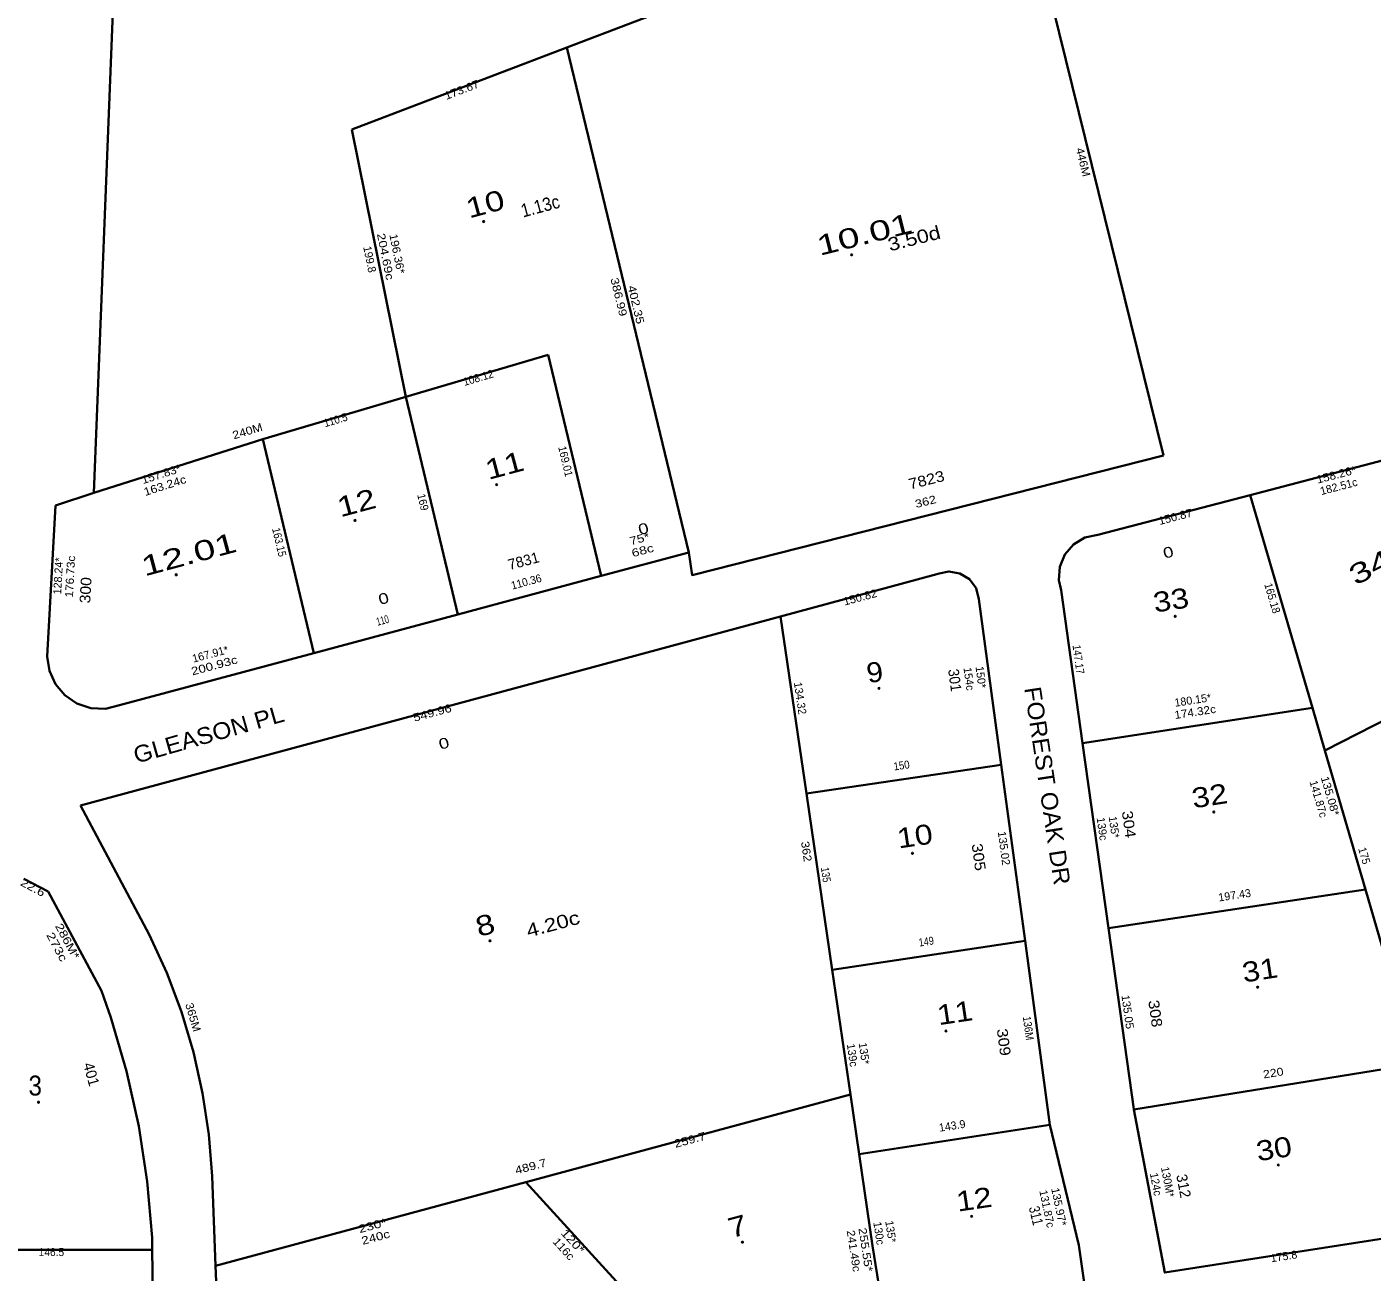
# Model space of a CAD drawing. Extents: x 2546959 to 2550387, y 581906 to 585027.
# Drawn here: x 2548228 to 2549237, y 583358 to 584292 of the extents above; entities that cross this region are included whole.
import ezdxf
from ezdxf.enums import TextEntityAlignment as Align

# ---------------------------------------------------------------- set-up
doc = ezdxf.new("R2010")
doc.units = 0
doc.header["$LTSCALE"] = 2.4
doc.header["$PDMODE"] = 32
doc.header["$PDSIZE"] = 1.2
for name, color, linetype in [('20', 7, 'Continuous'), ('38', 7, 'Continuous'), ('39', 7, 'Continuous'), ('41', 7, 'Continuous'), ('42', 7, 'Continuous')]:
    doc.layers.add(name, color=color, linetype=linetype)
doc.layers.add('40', color=7, linetype='Continuous', lineweight=35)

msp = doc.modelspace()

# ---------------------------------------------------------------- linework, layer by layer
at = {"layer": '40'}
for p, q in [((2548310.336, 584755.908), (2548278.336, 583942.322)), ((2548632.906, 584276.263), (2548972.05, 584405.537)), ((2548471.7, 584214.815), (2548632.906, 584276.263)), ((2548632.906, 584276.263), (2548724.329, 583897.607)), ((2548512.325, 584014.19), (2548471.7, 584214.815)), ((2548658.645, 583879.97), (2548619.071, 584045.736)), ((2548512.325, 584014.19), (2548405.115, 583982.508)), ((2548405.115, 583982.508), (2548278.336, 583942.322)), ((2548405.115, 583982.508), (2548443.168, 583822.113)), ((2549145.332, 583940.621), (2549272.401, 583973.833)), ((2548278.336, 583942.322), (2548249.659, 583932.695)), ((2549031.214, 583910.794), (2549145.332, 583940.621)), ((2549145.332, 583940.621), (2549192.015, 583780.951)), ((2548249.659, 583932.695), (2548243.372, 583819.636)), ((2548658.645, 583879.97), (2548724.329, 583897.607)), ((2548551.317, 583851.152), (2548658.645, 583879.97)), ((2548793.282, 583849.522), (2548910.499, 583881.177)), ((2549019.704, 583754.571), (2549003.678, 583869.22)), ((2548268.244, 583707.733), (2548793.282, 583849.522)), ((2548443.168, 583822.113), (2548551.317, 583851.152)), ((2548793.282, 583849.522), (2548812.656, 583716.826)), ((2548297.603, 583782.942), (2548443.168, 583822.113)), ((2549192.015, 583780.951), (2549019.704, 583754.571)), ((2549192.015, 583780.951), (2549201.357, 583749)), ((2549039.085, 583615.922), (2549019.704, 583754.571)), ((2548268.244, 583707.733), (2548319.879, 583611.016)), ((2548225.941, 583652.934), (2548244.139, 583643.253)), ((2549231.828, 583644.78), (2549039.085, 583615.922)), ((2548244.139, 583643.253), (2548284.022, 583568.754)), ((2549058.078, 583480.042), (2549039.085, 583615.922)), ((2548976.581, 583606.27), (2548995.202, 583468.491)), ((2549058.078, 583480.042), (2549058.121, 583479.818)), ((2548995.202, 583468.491), (2548852.159, 583446.26)), ((2548995.202, 583468.491), (2549016.87, 583378.193)), ((2548602.241, 583425.464), (2548369.6, 583362.624)), ((2548173.506, 583374.598), (2548322.179, 583374.593)), ((2548871.845, 583317.439), (2548862.168, 583377.706)), ((2549016.87, 583378.193), (2549022.401, 583339.578))]:
    msp.add_line(p, q, dxfattribs=at)
for points in [[(2548972.05, 584405.537), (2548972.954, 584405.881), (2549080.399, 583970.174)], [(2548619.071, 584045.736), (2548512.325, 584014.19), (2548551.317, 583851.152)], [(2548724.329, 583897.607), (2548726.889, 583880.611), (2549080.399, 583970.174)], [(2549003.678, 583869.22), (2549001.94, 583876.807), (2549002.568, 583886.777), (2549006.338, 583896.027), (2549012.857, 583903.596), (2549021.447, 583908.695), (2549031.214, 583910.794)], [(2548910.499, 583881.177), (2548912.166, 583881.737), (2548919.412, 583883.309), (2548927.705, 583881.91), (2548934.869, 583877.503), (2548939.857, 583870.73), (2548941.941, 583862.582)], [(2548941.941, 583862.582), (2548958.719, 583738.442), (2548976.581, 583606.27)], [(2549361.129, 583830.668), (2549201.357, 583749), (2549231.828, 583644.78), (2549250.655, 583580.386)], [(2548297.603, 583782.942), (2548286.951, 583780.42), (2548276.014, 583780.894), (2548265.62, 583784.329), (2548256.554, 583790.463), (2548249.501, 583798.834), (2548244.993, 583808.81), (2548243.372, 583819.636)], [(2548958.719, 583738.442), (2548812.656, 583716.826), (2548831.943, 583584.719)], [(2548319.879, 583611.016), (2548332.974, 583582.446), (2548344.033, 583553.027), (2548353, 583522.905), (2548359.831, 583492.227), (2548364.494, 583461.146), (2548366.966, 583429.815)], [(2548976.581, 583606.27), (2548831.943, 583584.719), (2548845.598, 583491.199)], [(2548284.022, 583568.754), (2548290.963, 583548.887), (2548302.841, 583508.518), (2548312.007, 583467.447), (2548318.419, 583425.856), (2548322.049, 583383.932)], [(2549270.052, 583514.047), (2549058.121, 583479.818), (2549081.302, 583357.597), (2549259.719, 583385.325)], [(2548845.598, 583491.199), (2548602.241, 583425.464), (2548680.492, 583339.561)], [(2548845.598, 583491.199), (2548852.159, 583446.26), (2548862.168, 583377.706)], [(2548366.966, 583429.815), (2548369.6, 583362.624), (2548371.931, 583303.172)], [(2548322.049, 583383.932), (2548322.179, 583374.593), (2548323.315, 583293.027)]]:
    msp.add_lwpolyline(points, dxfattribs=at)
at = {"layer": '41'}
for p in [(2548570.661, 584145.703), (2548846.468, 584120.717), (2548580.312, 583948.378), (2548474.143, 583921.567), (2548340.092, 583880.814), (2549089.131, 583849.719), (2548867.019, 583795.638), (2549118.102, 583702.931), (2548892.127, 583672.028), (2548575.376, 583606.359), (2549150.936, 583571.594), (2548917.235, 583538.76), (2548236.848, 583485.331), (2549166.387, 583438.327), (2548936.549, 583399.697), (2548764.653, 583380.383)]:
    msp.add_point(p, dxfattribs=at)

# ---------------------------------------------------------------- texts
at = {"layer": '20', "width": 1.1}
for s, rotation, p in [('FOREST OAK DR', 278.597, (2548987.115, 583721.671)), ('GLEASON PL', 15.913, (2548366.146, 583755.161))]:
    msp.add_text(s, height=12.5, rotation=rotation, dxfattribs=at).set_placement(p, align=Align.CENTER)
at = {"layer": '38'}
for s, rotation, width, p in [('10', 15.03, 1.3, (2548573.686, 584151.698)), ('10.01', 14.217, 1.45, (2548857.843, 584128.848)), ('11', 15.03, 1.3, (2548588.129, 583955.653)), ('12', 15.03, 1.3, (2548477.154, 583927.593)), ('12.01', 15.03, 1.45, (2548351.457, 583888.976)), ('34', 27.074, 1.45, (2549238.674, 583879.825)), ('33', 8.834, 1.2, (2549087.084, 583854.487)), ('9', 8.418, 1.1, (2548864.951, 583800.401)), ('32', 8.834, 1.2, (2549116.043, 583707.715)), ('10', 8.418, 1.2, (2548894.977, 583677.502)), ('8', 15.116, 1.25, (2548573.663, 583611.009)), ('31', 8.834, 1.2, (2549153.745, 583577.065)), ('11', 8.418, 1.2, (2548925.003, 583545.002)), ('30', 8.834, 1.2, (2549164.308, 583443.078)), ('12', 8.418, 1.2, (2548939.403, 583405.184)), ('7', 15.116, 1.25, (2548762.939, 583385.091))]:
    msp.add_text(s, height=15, rotation=rotation, dxfattribs=dict(at, width=width)).set_placement(p, align=Align.CENTER)
at = {"layer": '38', "width": 0.9}
msp.add_text('3', height=15, dxfattribs=at).set_placement((2548234.368, 583490.331), align=Align.CENTER)
at = {"layer": '39'}
for s, rotation, width, p in [('7823', 14.217, 1.15, (2548903.6, 583948.07)), ('0', 15.03, 1.3, (2548691.447, 583911.528)), ('0', 14.648, 1.3, (2549084.935, 583893.801)), ('300', 86.817, 1.1, (2548276.103, 583869.032)), ('0', 15.03, 1.3, (2548496.623, 583859.155)), ('301', 277.697, 0.95, (2548919.95, 583801.259)), ('0', 15.113, 1.3, (2548541.859, 583750.574)), ('304', 277.958, 1.15, (2549050.494, 583693.208)), ('305', 277.697, 1.15, (2548937.901, 583668.602)), ('308', 277.957, 1.15, (2549070.334, 583551.235)), ('309', 277.697, 1.15, (2548956.675, 583529.832)), ('311', 283.493, 0.8, (2548980.952, 583399.362))]:
    msp.add_text(s, height=8, rotation=rotation, dxfattribs=dict(at, width=width)).set_placement(p, align=Align.CENTER)
for s, rotation, p in [('7831', 15.03, (2548601.537, 583887.365)), ('401', 285.442, (2548272.632, 583505.239)), ('312', 280.74, (2549091.529, 583421.792))]:
    msp.add_text(s, height=8, rotation=rotation, dxfattribs=at).set_placement(p, align=Align.CENTER)
at = {"layer": '42'}
for s, rotation, width, p in [('173.67', 20.866, 1.1, (2548555.269, 584241.682)), ('446M', 283.853, 1.1, (2549017.197, 584189.551)), ('204.69c', 281.447, 1.25, (2548494.08, 584118.863)), ('196.36*', 281.447, 1.1, (2548502.858, 584120.94)), ('386.99', 283.574, 1.2, (2548669.084, 584088.459)), ('402.35', 283.362, 1.2, (2548681.983, 584082.721)), ('108.12', 16.463, 0.95, (2548567.419, 584025.694)), ('110.5', 16.463, 0.9, (2548460.435, 583994.015)), ('240M', 17.074, 1.15, (2548394.396, 583985.724)), ('169.01', 283.427, 0.95, (2548629.159, 583965.205)), ('157.83*', 17.767, 1.1, (2548329.732, 583953.429)), ('158.26*', 14.648, 1.1, (2549210.627, 583952.991)), ('163.24c', 17.767, 1.15, (2548332.506, 583944.896)), ('169', 283.45, 0.95, (2548522.22, 583934.6)), ('362', 14.217, 1.2, (2548902.686, 583932.802)), ('150.87', 14.648, 1.05, (2549089.988, 583921.418)), ('163.15', 283.347, 0.9, (2548414.452, 583904.578)), ('75*', 15.03, 1.25, (2548688.212, 583904.888)), ('68c', 15.03, 1.3, (2548690.559, 583896.142)), ('176.73c', 86.817, 1.1, (2548263.512, 583879.357)), ('110.36', 15.03, 0.95, (2548603.324, 583872.693)), ('150.82', 15.112, 1.05, (2548853.666, 583861.06)), ('165.18', 286.297, 0.95, (2549159.111, 583862.459)), ('110', 15.03, 0.7, (2548495.591, 583843.785)), ('147.17', 277.957, 0.9, (2549013.66, 583816.936)), ('200.93c', 15.061, 1.25, (2548369.446, 583809.956)), ('549.96', 15.113, 1.2, (2548532.915, 583774.438)), ('174.32c', 8.704, 1.1, (2549104.517, 583775.026)), ('150', 8.418, 0.9, (2548884.384, 583734.914)), ('135.08*', 286.298, 1.1, (2549202.469, 583714.152)), ('135.02', 277.697, 1.05, (2548957.815, 583675.363)), ('362', 278.307, 1.15, (2548809.668, 583672.898)), ('175', 286.298, 0.95, (2549228.068, 583669.351)), ('135', 278.307, 0.85, (2548824.28, 583655.458)), ('22.6', 331.989, 1.25, (2548231.249, 583643.699)), ('286M*', 298.162, 1.25, (2548255.922, 583604.693)), ('273c', 298.162, 1.35, (2548248.028, 583600.426)), ('149', 8.474, 0.85, (2548902.894, 583602.863)), ('135.05', 277.957, 1.05, (2549050.564, 583552.67)), ('365M', 286.367, 1.1, (2548349.895, 583548.215)), ('136M', 277.697, 0.9, (2548976.055, 583540.431)), ('220', 9.175, 1.15, (2549163.125, 583504.377)), ('259.7', 15.116, 1.2, (2548726.085, 583454.229)), ('489.7', 15.116, 1.2, (2548606.674, 583434.283)), ('135.97*', 281.914, 1.05, (2548999.074, 583406.34)), ('230*', 15.116, 1.3, (2548488.062, 583389.909)), ('240c', 15.116, 1.25, (2548490.408, 583381.163)), ('116c', 312.331, 1.1, (2548628.436, 583373.326)), ('120*', 312.331, 1.3, (2548635.304, 583379.02)), ('241.49c', 278.734, 1.1, (2548845.192, 583373.391)), ('255.55*', 278.734, 1.2, (2548854.103, 583374.297)), ('146.5', 359.998, 0.95, (2548246.497, 583369.967))]:
    msp.add_text(s, height=5.999, rotation=rotation, dxfattribs=dict(at, width=width)).set_placement(p, align=Align.CENTER)
for s, rotation, width, p in [('1.13c', 15.03, 0.9, (2548600.11, 584148.681)), ('3.50d', 14.217, 1.2, (2548875.13, 584123.277)), ('4.20c', 15.116, 1.25, (2548604.115, 583608.741))]:
    msp.add_text(s, height=10, rotation=rotation, dxfattribs=dict(at, width=width)).set_placement(p)
for s, rotation, p in [('199.8', 281.447, (2548482.272, 584116.78)), ('182.51c', 14.648, (2549212.501, 583944.149)), ('128.24*', 86.817, (2548254.552, 583879.784)), ('167.91*', 15.061, (2548366.37, 583818.506)), ('154c', 277.697, (2548931.523, 583802.401)), ('150*', 277.697, (2548940.482, 583803.682)), ('134.32', 278.307, (2548804.975, 583787.831)), ('180.15*', 8.704, (2549102.757, 583783.928)), ('141.87c', 286.298, (2549193.723, 583711.954)), ('139c', 277.958, (2549031.419, 583689.949)), ('135*', 277.958, (2549040.379, 583691.229)), ('197.43', 8.515, (2549134.096, 583637.637)), ('139c', 278.307, (2548844.12, 583520.207)), ('135*', 278.307, (2548852.973, 583521.487)), ('143.9', 8.834, (2548922.345, 583464.737)), ('130M*', 280.74, (2549080.591, 583425.021)), ('124c', 280.74, (2549071.736, 583423.314)), ('131.87c', 281.914, (2548990.142, 583404.788)), ('130c', 278.688, (2548864.072, 583386.621)), ('135*', 278.688, (2548872.925, 583387.902)), ('175.8', 8.834, (2549171.035, 583366.819))]:
    msp.add_text(s, height=5.999, rotation=rotation, dxfattribs=at).set_placement(p, align=Align.CENTER)

doc.saveas('drawing.dxf')
